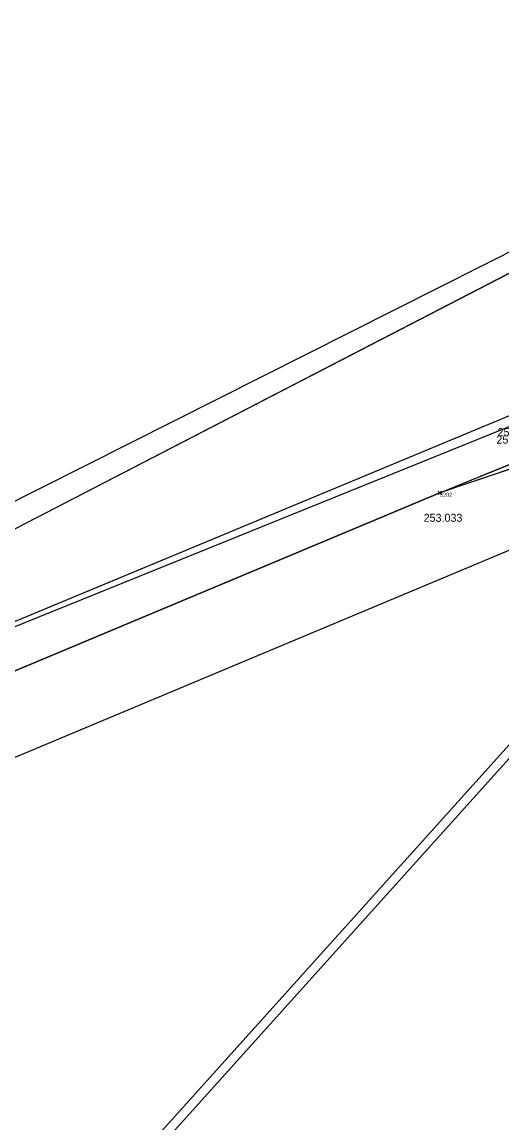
# Model space of a CAD drawing. Extents: x -809973 to -809318, y -1011363 to -1010505.
# Drawn here: x -809870.63 to -809864.63, y -1010885.13 to -1010871.39 of the extents above; entities that cross this region are included whole.
import ezdxf

# ---------------------------------------------------------------- set-up
doc = ezdxf.new("R2010")
doc.units = 0
for name, color, linetype in [('18b - zaměření - čísla bodů', 7, 'Continuous'), ('18c - zaměření - výšky', 7, 'Continuous'), ('SO05 - Úprava kabelů', 7, 'Continuous'), ('SO_02', 7, 'Continuous'), ('stav_stav', 7, 'Continuous')]:
    doc.layers.add(name, color=color, linetype=linetype)

# ---------------------------------------------------------------- blocks, each defined once
blk = doc.blocks.new('POINT_DISPLAY')
for p, q in [((-0.021, -0.021), (0.021, 0.021)), ((-0.021, 0.021), (0.021, -0.021))]:
    blk.add_line(p, q)

msp = doc.modelspace()

# ---------------------------------------------------------------- linework, layer by layer
at = {"layer": 'SO05 - Úprava kabelů'}
for points in [[(-809832.494, -1011018.409), (-809834.046, -1011017.811), (-809840.102, -1011020.003), (-809840.886, -1011019.699), (-809849.784, -1011002.747), (-809854.105, -1010999.74), (-809859.871, -1010979.608), (-809861.054, -1010971.463), (-809873.181, -1010917.053), (-809875.79, -1010892.925), (-809862.192, -1010877.803), (-809870.3, -1010824.924)], [(-809832.452, -1011018.3), (-809834.045, -1011017.686), (-809840.101, -1011019.878), (-809840.803, -1011019.606), (-809849.694, -1011002.668), (-809854.004, -1010999.668), (-809859.756, -1010979.584), (-809860.94, -1010971.442), (-809873.066, -1010917.034), (-809875.669, -1010892.964), (-809862.069, -1010877.84), (-809862.069, -1010877.84), (-809870.184, -1010824.906)]]:
    msp.add_lwpolyline(points, dxfattribs=at)
at = {"layer": 'SO_02'}
for p, q in [((-809876.864, -1010880.47), (-809863.32, -1010873.645)), ((-809864.417, -1010876.396), (-809876.573, -1010881.314))]:
    msp.add_line(p, q, dxfattribs=at)
for points in [[(-809880.813, -1010883.644), (-809881.049, -1010884.006), (-809881.035, -1010883.822), (-809875.603, -1010880.245), (-809863.086, -1010873.774), (-809863.071, -1010873.493), (-809863.052, -1010873.86)], [(-809862.712, -1010876.25), (-809862.734, -1010876.278), (-809864.222, -1010876.871), (-809865.405, -1010877.268), (-809864.223, -1010876.786), (-809862.712, -1010876.25), (-809862.769, -1010876.151)], [(-809864.497, -1010876.291), (-809876.573, -1010881.314), (-809880.813, -1010883.644)], [(-809865.405, -1010877.268), (-809876.323, -1010881.843), (-809880.73, -1010884.265), (-809881.049, -1010884.006)], [(-809862.873, -1010877.291), (-809875.888, -1010882.745), (-809880.049, -1010885.032)]]:
    msp.add_lwpolyline(points, dxfattribs=at)
at = {"layer": 'stav_stav'}
for p, q in [((-809875.603, -1010880.245), (-809863.086, -1010873.774)), ((-809864.497, -1010876.291), (-809876.573, -1010881.314)), ((-809864.417, -1010876.396), (-809876.573, -1010881.314)), ((-809865.405, -1010877.268), (-809864.223, -1010876.786)), ((-809864.222, -1010876.871), (-809865.405, -1010877.268)), ((-809864.222, -1010876.871), (-809865.405, -1010877.268)), ((-809865.405, -1010877.268), (-809876.323, -1010881.843)), ((-809876.323, -1010881.843), (-809865.405, -1010877.268))]:
    msp.add_line(p, q, dxfattribs=at)

# ---------------------------------------------------------------- block references
at = {"layer": '18b - zaměření - čísla bodů'}
msp.add_blockref('POINT_DISPLAY', (-809865.405, -1010877.268), dxfattribs=at)

# ---------------------------------------------------------------- texts
msp.add_text('5202', height=0.05, dxfattribs=at).set_placement((-809865.405, -1010877.318))
at = {"layer": '18c - zaměření - výšky'}
for s, p in [('253.600', (-809864.685, -1010876.561)), ('253.772', (-809864.699, -1010876.654)), ('253.033', (-809865.608, -1010877.631))]:
    msp.add_text(s, height=0.1, dxfattribs=at).set_placement(p)

doc.saveas('drawing.dxf')
